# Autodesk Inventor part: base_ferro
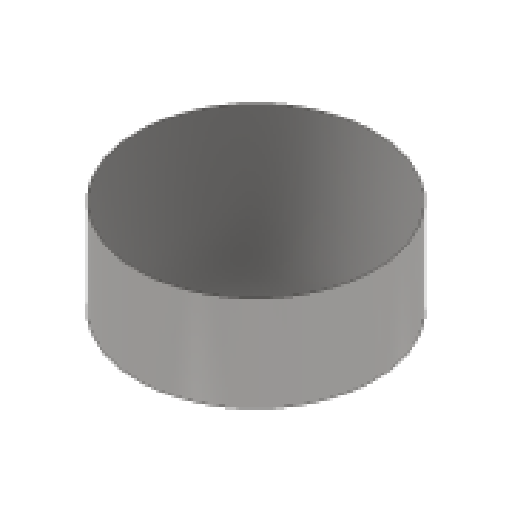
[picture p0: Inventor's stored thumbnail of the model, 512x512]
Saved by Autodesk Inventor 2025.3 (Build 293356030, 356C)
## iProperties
Created: 2026-01
Part Number: base_ferro
Material: Acciaio
Document SubType Name: Modeling
Designer: Ryzen5700u
Density: 7.85 g/cm^3
Appearance: Acciaio - Lucido
Mass: 7039.17 g
Surface Area: 726.938 cm^2
Volume: 896.709 cm^3
Author: Ryzen5700u
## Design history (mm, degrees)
sketch "Schizzo1"
  geometry: C1 r 50 at (0, 0); 1 further point
  constraints: 1 centre point, 1 coincident
  dimensions: "d0" = 100 diameter of C1
extrude "Estrusione1" new body sketch "Schizzo1" distance "d1" = 40; taper "d2" = 0 deg
sketch "Schizzo3"
  geometry: L1 (0, 0)-(42, 0)
  constraints: 2 end point, 1 horizontal
  dimensions: "d14" = 42 distance of L1.start L1.end
hole "Foro2" sketch "Schizzo3" at (42, 0) diameter "d15" = 5.3; stored, may be unused: countersink angle "d19" = 90 deg, drill point angle "d21" = 118 deg; dims "d16" = 6, "d17" = 9, "d18" = 15, "d20" = 8
pattern_circular "Serie circolare2" dims angle "d23" = 360 deg
node "Solido1"
